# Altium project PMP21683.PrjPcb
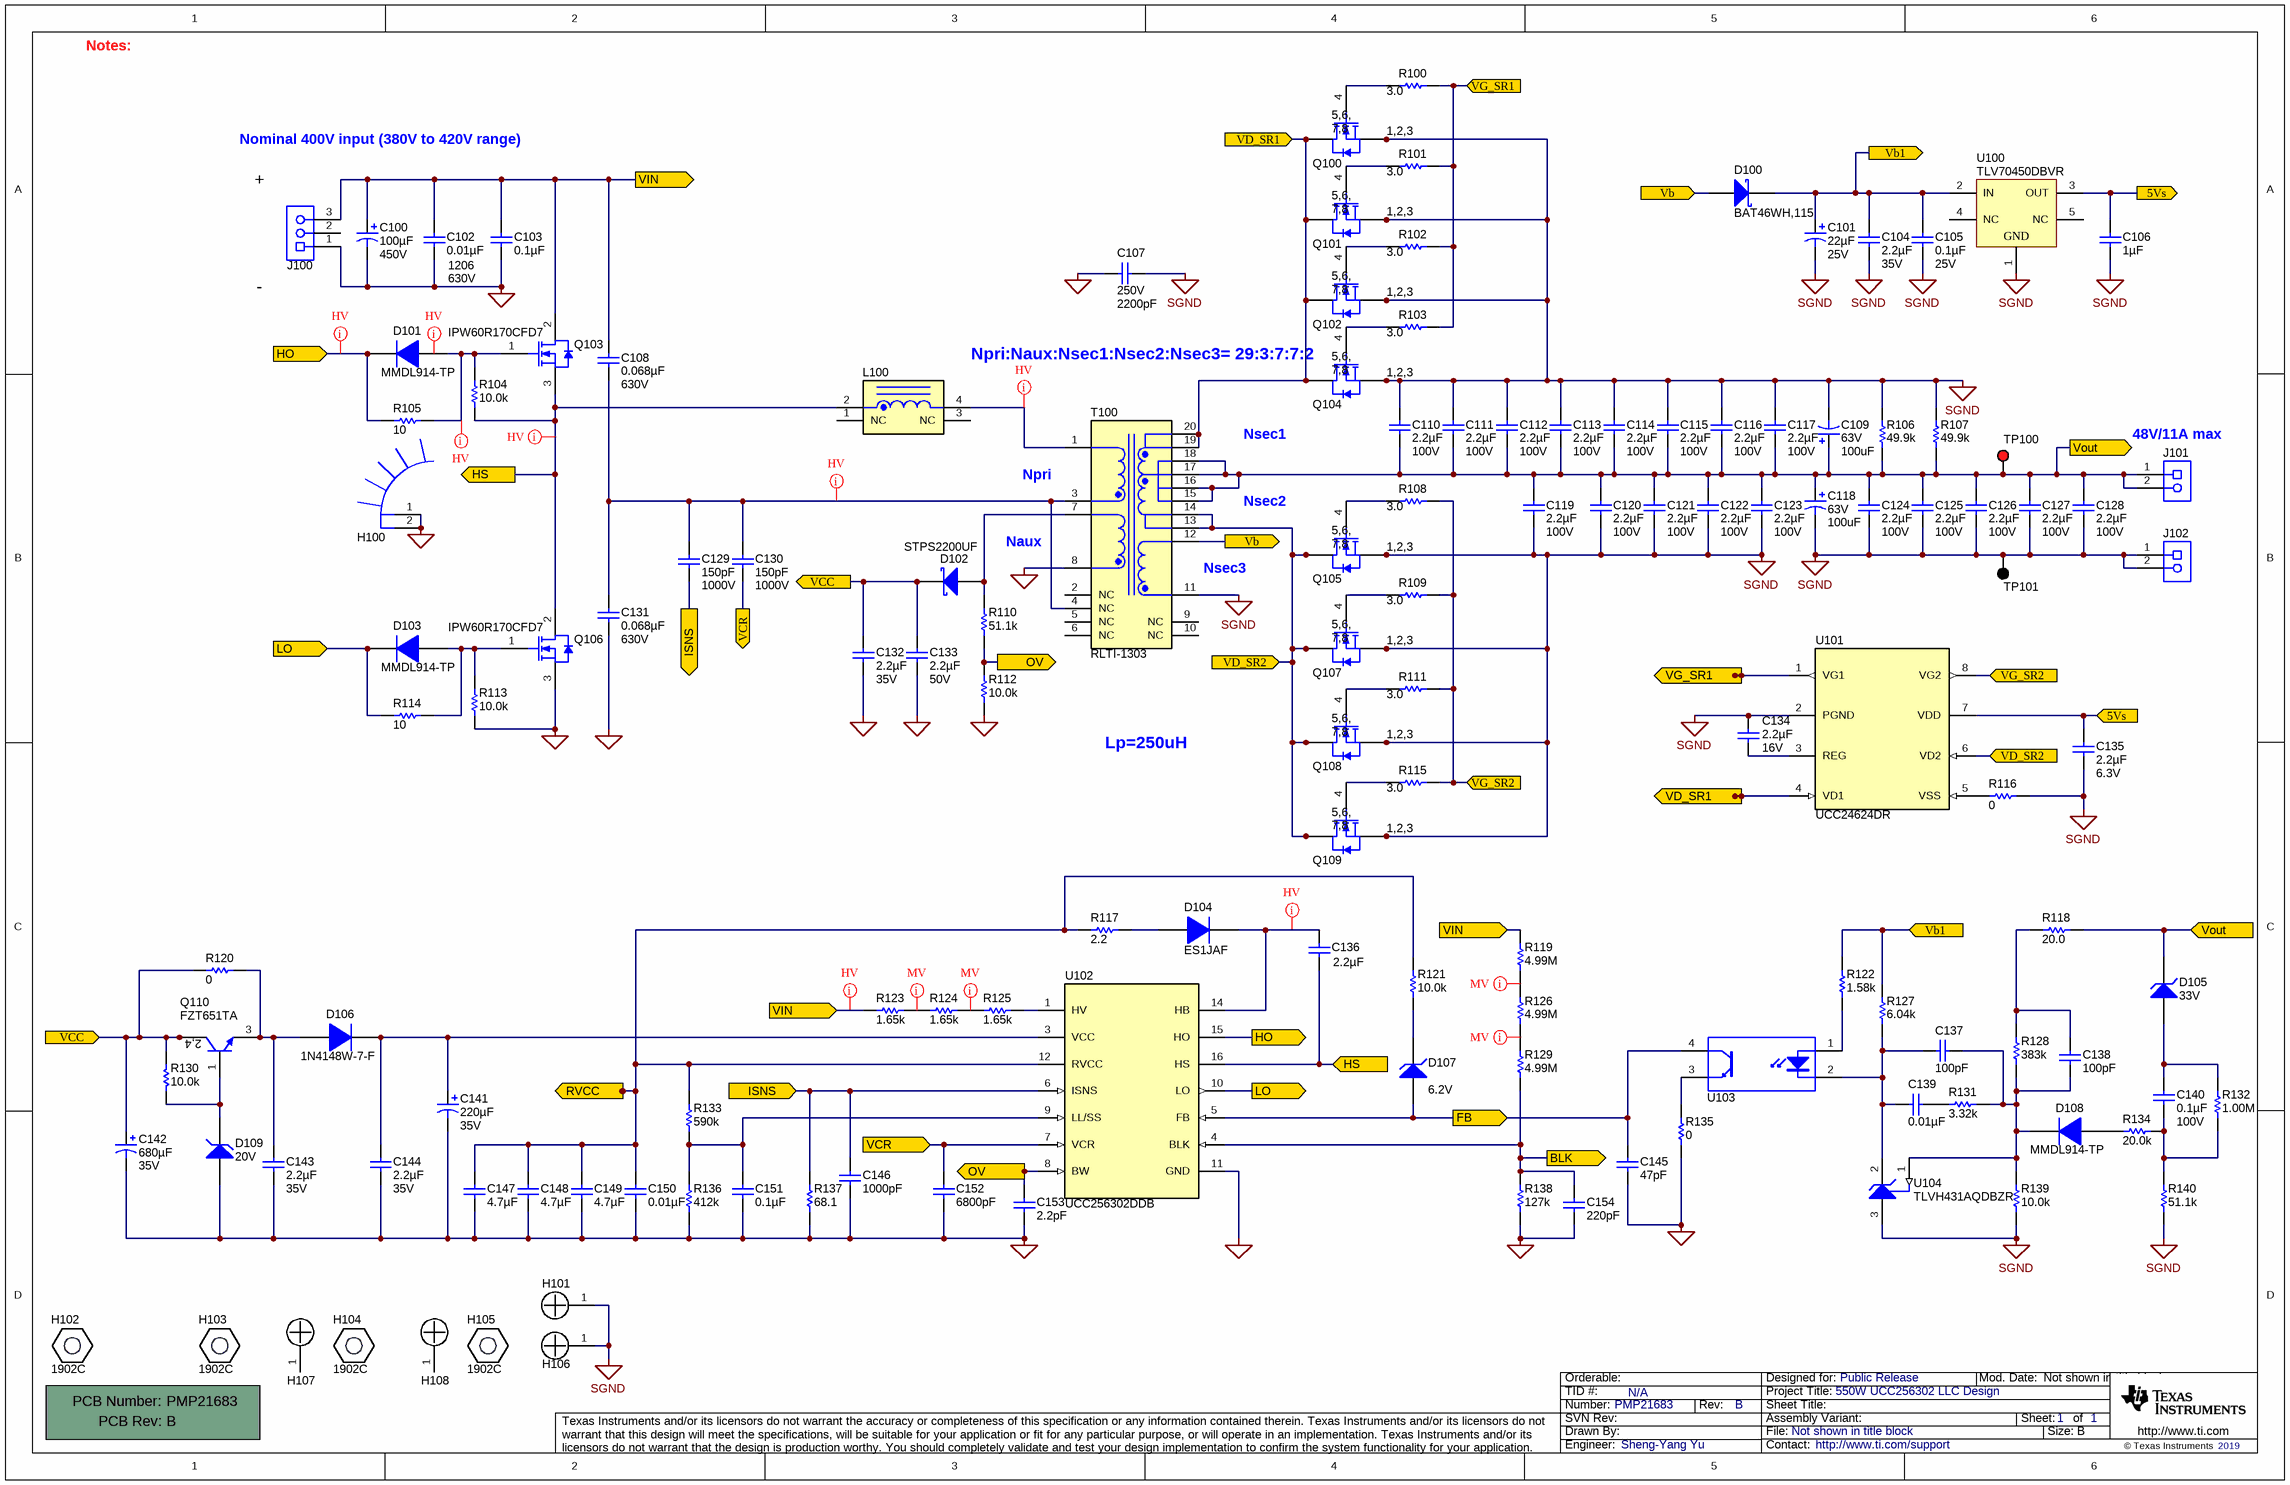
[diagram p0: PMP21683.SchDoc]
CopyrightYear: 2019; PCB_Layout: Sheng-Yang Yu; PCB_Rev: B; PRJ_Customer: Public Release; PRJ_Engineer: Sheng-Yang Yu; PRJ_Number: PMP21683; PRJ_Title: 550W UCC256302 LLC Design; SCH_Rev: B; TechSupport: http://www.ti.com/support; TID: N/A
1 sheet, 139 parts. Net scope: flat (ports and power ports of the same name join across sheets).
Board file: PMP21683.PcbDoc

## Sheet PMP21683.SchDoc
size 431 x 279 mm; Date: Not shown in title block; ApprovedBy: Not shown in title block; CheckedBy: Not shown in title block; Author: Not shown in title block; CompanyName: Not shown in title block; Engineer: Not shown in title block; Organization: Not shown in title block; Address1: Not shown in title block; Address2: Not shown in title block; Address3: Not shown in title block; Address4: Not shown in title block; DocumentNumber: 1; Revision: Use project parameter SCH_Rev; SheetNumber: 1; SheetTotal: 1; PageSetup: Record=PageOptions¦CenterHorizontal=True¦CenterVertical=True¦PrintScale=1.00¦XCorrection=1.00¦YCorrection=1.00¦PrintKind=0¦BorderSize=5000000¦LeftOffset=0¦BottomOffset=0¦Orientation=2¦PaperLength=1000¦PaperWidth=1000¦Scale=100¦PaperSource=15¦PrintQuality=600¦MediaType=1¦DitherType=10¦PaperKind=Letter¦PrintScaleMode=1

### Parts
!PCB100  Printed Circuit Board  (value not drawn)  (mechanical)
C100  ValueDisplayed: 100µF  Value2: 450V  [VR_1600x2500]  (hidden comment: 860241480001)
C101  ValueDisplayed: 22µF  Value2: 25V  [ML_500x500]  (hidden comment: 25ML22MEFC5X5)
C102  ValueDisplayed: 0.01µF  Value2: 630V  [1206]  (hidden comment: GRM31BR72J103KW01L)
C103  ValueDisplayed: 0.1µF  [1812_254]  (hidden comment: C1812W104KDRACTU)
C104  ValueDisplayed: 2.2µF  Value2: 35V  [0603]  (hidden comment: GRM188R6YA225KA12D)
C105  ValueDisplayed: 0.1µF  Value2: 25V  [0603]  (hidden comment: 06033C104JAT2A)
C106  ValueDisplayed: 1µF  [0603]  (hidden comment: GRM185R61A105KE36D)
C107  VDC_V: 250V  ValueDisplayed: 2200pF  [CAPRD1000W60D1000H1400]  (hidden comment: DE1E3KX222MA5BA01)
C108  ValueDisplayed: 0.068µF  VDC_V: 630V  [WCAP-FTBP_1800x600x1200]  (hidden comment: 890303325004CS)
C109  VDC_V: 63V  ValueDisplayed: 100uF  [CR_1000x1270]  (hidden comment: PCR1J101MCL1GS)
C110  ValueDisplayed: 2.2µF  Value2: 100V  [1206_190]  (hidden comment: GRM31CR72A225KA73L)
C111  ValueDisplayed: 2.2µF  Value2: 100V  [1206_190]  (hidden comment: GRM31CR72A225KA73L)
C112  ValueDisplayed: 2.2µF  Value2: 100V  [1206_190]  (hidden comment: GRM31CR72A225KA73L)
C113  ValueDisplayed: 2.2µF  Value2: 100V  [1206_190]  (hidden comment: GRM31CR72A225KA73L)
C114  ValueDisplayed: 2.2µF  Value2: 100V  [1206_190]  (hidden comment: GRM31CR72A225KA73L)
C115  ValueDisplayed: 2.2µF  Value2: 100V  [1206_190]  (hidden comment: GRM31CR72A225KA73L)
C116  ValueDisplayed: 2.2µF  Value2: 100V  [1206_190]  (hidden comment: GRM31CR72A225KA73L)
C117  ValueDisplayed: 2.2µF  Value2: 100V  [1206_190]  (hidden comment: GRM31CR72A225KA73L)
C118  VDC_V: 63V  ValueDisplayed: 100uF  [CR_1000x1270]  (hidden comment: PCR1J101MCL1GS)
C119  ValueDisplayed: 2.2µF  Value2: 100V  [1206_190]  (hidden comment: GRM31CR72A225KA73L)
C120  ValueDisplayed: 2.2µF  Value2: 100V  [1206_190]  (hidden comment: GRM31CR72A225KA73L)
C121  ValueDisplayed: 2.2µF  Value2: 100V  [1206_190]  (hidden comment: GRM31CR72A225KA73L)
C122  ValueDisplayed: 2.2µF  Value2: 100V  [1206_190]  (hidden comment: GRM31CR72A225KA73L)
C123  ValueDisplayed: 2.2µF  Value2: 100V  [1206_190]  (hidden comment: GRM31CR72A225KA73L)
C124  ValueDisplayed: 2.2µF  Value2: 100V  [1206_190]  (hidden comment: GRM31CR72A225KA73L)
C125  ValueDisplayed: 2.2µF  Value2: 100V  [1206_190]  (hidden comment: GRM31CR72A225KA73L)
C126  ValueDisplayed: 2.2µF  Value2: 100V  [1206_190]  (hidden comment: GRM31CR72A225KA73L)
C127  ValueDisplayed: 2.2µF  Value2: 100V  [1206_190]  (hidden comment: GRM31CR72A225KA73L)
C128  ValueDisplayed: 2.2µF  Value2: 100V  [1206_190]  (hidden comment: GRM31CR72A225KA73L)
C129  ValueDisplayed: 150pF  Value2: 1000V  [1206]  (hidden comment: GRM31A7U3A151JW31D)
C130  ValueDisplayed: 150pF  Value2: 1000V  [1206]  (hidden comment: GRM31A7U3A151JW31D)
C131  ValueDisplayed: 0.068µF  VDC_V: 630V  [WCAP-FTBP_1800x600x1200]  (hidden comment: 890303325004CS)
C132  ValueDisplayed: 2.2µF  Value2: 35V  [0603]  (hidden comment: GRM188R6YA225KA12D)
C133  ValueDisplayed: 2.2µF  Value2: 50V  [1206_180]  (hidden comment: C3216X5R1H225K160AB)
C134  ValueDisplayed: 2.2µF  Value2: 16V  [0603]  (hidden comment: 885012106018)
C135  ValueDisplayed: 2.2µF  Value2: 6.3V  [0603]  (hidden comment: C0603C225K9PACTU)
C136  ValueDisplayed: 2.2µF  [1206]  (hidden comment: C1206C225K4RACTU)
C137  ValueDisplayed: 100pF  [0603]  (hidden comment: 06035A101JAT2A)
C138  ValueDisplayed: 100pF  [0603]  (hidden comment: 06035A101JAT2A)
C139  ValueDisplayed: 0.01µF  [0603]  (hidden comment: 885012206040)
C140  ValueDisplayed: 0.1µF  Value2: 100V  [1206]  (hidden comment: GRM319R72A104KA01D)
C141  ValueDisplayed: 220µF  Value2: 35V  [KL_1000x2000]  (hidden comment: 860080575012)
C142  ValueDisplayed: 680µF  Value2: 35V  [HW_1000x2000]  (hidden comment: 860040575012)
C143  ValueDisplayed: 2.2µF  Value2: 35V  [0603]  (hidden comment: GRM188R6YA225KA12D)
C144  ValueDisplayed: 2.2µF  Value2: 35V  [0603]  (hidden comment: GRM188R6YA225KA12D)
C145  ValueDisplayed: 47pF  [0603]  (hidden comment: GRM1885C1H470FA01J)
C146  ValueDisplayed: 1000pF  [0603]  (hidden comment: C0603X102K5RACTU)
C147  ValueDisplayed: 4.7µF  [0603]  (hidden comment: GRM188R61C475KAAJ)
C148  ValueDisplayed: 4.7µF  [0603]  (hidden comment: GRM188R61C475KAAJ)
C149  ValueDisplayed: 4.7µF  [0603]  (hidden comment: GRM188R61C475KAAJ)
C150  ValueDisplayed: 0.01µF  [0603]  (hidden comment: 06031C103JAT2A)
C151  ValueDisplayed: 0.1µF  [0603]  (hidden comment: 0603YC104JAT2A)
C152  ValueDisplayed: 6800pF  [0603]  (hidden comment: 06031C682KAT2A)
C153  ValueDisplayed: 2.2pF  [0603]  (hidden comment: 06035A2R2CAT2A)
C154  ValueDisplayed: 220pF  [0603]  (hidden comment: GRM188R71H221KA01D)
D100  BAT46WH,115  [SOD-123F]
D101  MMDL914-TP  [SOD-323]
D102  STPS2200UF  [SMB_flat]
D103  MMDL914-TP  [SOD-323]
D104  ES1JAF  [SMAF]
D105  value 33V  [SOD-123]  (hidden comment: MMSZ5257B-7-F)
D106  1N4148W-7-F  [SOD-123]
D107  value 6.2V  [SOD-123]  (hidden comment: MMSZ5234B-7-F)
D108  MMDL914-TP  [SOD-323]
D109  value 20V  [SOD-323]  (hidden comment: MMSZ5250BS-7-F)
H100  513002B02500G  [Aavid_513002B02500G]  (value not drawn)
H101  NY PMS 440 0025 PH  [NY PMS 440 0025 PH]  (value not drawn)
H102  1902C  [Keystone_1902C]
H103  1902C  [Keystone_1902C]
H104  1902C  [Keystone_1902C]
H105  1902C  [Keystone_1902C]
H106  NY PMS 440 0025 PH  [NY PMS 440 0025 PH]  (value not drawn)
H107  NY PMS 440 0025 PH  [NY PMS 440 0025 PH]  (value not drawn)
H108  NY PMS 440 0025 PH  [NY PMS 440 0025 PH]  (value not drawn)
J100  282856-3  [TE_282856-3]  (value not drawn)
J101  1715721  [PhoenixContact_1715721]  (value not drawn)
J102  1715721  [PhoenixContact_1715721]  (value not drawn)
L100  RLTI-1304  [RLTI-1304]  (value not drawn)
Q100  BSC320N20NS3 G  [PG-TDSON-8]  (value not drawn)
Q101  BSC320N20NS3 G  [PG-TDSON-8]  (value not drawn)
Q102  BSC320N20NS3 G  [PG-TDSON-8]  (value not drawn)
Q103  PartNumber: IPW60R170CFD7  [TO-247]  (hidden comment: IPW60R075CPFKSA1)
Q104  BSC320N20NS3 G  [PG-TDSON-8]  (value not drawn)
Q105  BSC320N20NS3 G  [PG-TDSON-8]  (value not drawn)
Q106  PartNumber: IPW60R170CFD7  [TO-247]  (hidden comment: IPW60R075CPFKSA1)
Q107  BSC320N20NS3 G  [PG-TDSON-8]  (value not drawn)
Q108  BSC320N20NS3 G  [PG-TDSON-8]  (value not drawn)
Q109  BSC320N20NS3 G  [PG-TDSON-8]  (value not drawn)
Q110  FZT651TA  [SOT-223]
R100  ValueDisplayed: 3.0  [0402]  (hidden comment: CRCW04023R00JNED)
R101  ValueDisplayed: 3.0  [0402]  (hidden comment: CRCW04023R00JNED)
R102  ValueDisplayed: 3.0  [0402]  (hidden comment: CRCW04023R00JNED)
R103  ValueDisplayed: 3.0  [0402]  (hidden comment: CRCW04023R00JNED)
R104  ValueDisplayed: 10.0k  [0805_HV]  (hidden comment: RG2012P-103-B-T5)
R105  ValueDisplayed: 10  [0805_HV]  (hidden comment: RC0805JR-0710RL)
R106  ValueDisplayed: 49.9k  [1206]  (hidden comment: CRCW120649K9FKEA)
R107  ValueDisplayed: 49.9k  [1206]  (hidden comment: CRCW120649K9FKEA)
R108  ValueDisplayed: 3.0  [0402]  (hidden comment: CRCW04023R00JNED)
R109  ValueDisplayed: 3.0  [0402]  (hidden comment: CRCW04023R00JNED)
R110  ValueDisplayed: 51.1k  [0603]  (hidden comment: CRCW060351K1FKEA)
R111  ValueDisplayed: 3.0  [0402]  (hidden comment: CRCW04023R00JNED)
R112  ValueDisplayed: 10.0k  [0603]  (hidden comment: RCG060310K0FKEA)
R113  ValueDisplayed: 10.0k  [0805_HV]  (hidden comment: RG2012P-103-B-T5)
R114  ValueDisplayed: 10  [0805_HV]  (hidden comment: RC0805JR-0710RL)
R115  ValueDisplayed: 3.0  [0402]  (hidden comment: CRCW04023R00JNED)
R116  ValueDisplayed: 0  [0603]  (hidden comment: RMCF0603ZT0R00)
R117  ValueDisplayed: 2.2  [0603]  (hidden comment: CRCW06032R20JNEA)
R118  ValueDisplayed: 20.0  [0603]  (hidden comment: CRCW060320R0FKEA)
R119  ValueDisplayed: 4.99M  [1206]  (hidden comment: CRCW12064M99FKEA)
R120  ValueDisplayed: 0  [2010]  (hidden comment: CRCW20100000Z0EF)
R121  ValueDisplayed: 10.0k  [0603]  (hidden comment: ERJ-3EKF1002V)
R122  ValueDisplayed: 1.58k  [0603]  (hidden comment: RG1608P-1581-B-T5)
R123  ValueDisplayed: 1.65k  [1206]  (hidden comment: CRCW12061K65FKEA)
R124  ValueDisplayed: 1.65k  [1206]  (hidden comment: CRCW12061K65FKEA)
R125  ValueDisplayed: 1.65k  [1206]  (hidden comment: CRCW12061K65FKEA)
R126  ValueDisplayed: 4.99M  [1206]  (hidden comment: CRCW12064M99FKEA)
R127  ValueDisplayed: 6.04k  [0603]  (hidden comment: CRCW06036K04FKEA)
R128  ValueDisplayed: 383k  [0603]  (hidden comment: CRCW0603383KFKEA)
R129  ValueDisplayed: 4.99M  [1206]  (hidden comment: CRCW12064M99FKEA)
R130  ValueDisplayed: 10.0k  [0603]  (hidden comment: CRCW060310K0FKEA)
R131  ValueDisplayed: 3.32k  [0603]  (hidden comment: CRCW06033K32FKEA)
R132  ValueDisplayed: 1.00M  [1206]  (hidden comment: CRCW12061M00FKEA)
R133  ValueDisplayed: 590k  [0603]  (hidden comment: CRCW0603590KFKEA)
R134  ValueDisplayed: 20.0k  [0603]  (hidden comment: RC0603FR-0720KL)
R135  ValueDisplayed: 0  [5108]  (hidden comment: 5108)
R136  ValueDisplayed: 412k  [0603]  (hidden comment: CRCW0603412KFKEA)
R137  ValueDisplayed: 68.1  [0603]  (hidden comment: CRCW060368R1FKEA)
R138  ValueDisplayed: 127k  [0603]  (hidden comment: CRCW0603127KFKEA)
R139  ValueDisplayed: 10.0k  [0603]  (hidden comment: RCG060310K0FKEA)
R140  ValueDisplayed: 51.1k  [0603]  (hidden comment: CRCW060351K1FKEA)
T100  RLTI-1303  [Renco_RLTI-1303]
TP100  5000  [Keystone5000]  (value not drawn)
TP101  5011  [Keystone5011]  (value not drawn)
U100  TLV70450DBVR  [DBV0005A_N]
U101  UCC24624DR  [D0008A_N]
U102  UCC256302DDB  [DDB0014A]
U103  VO618A-3  [DIP-4]  (value not drawn)
U104  TLVH431AQDBZR  [DBZ0003A_N]

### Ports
5Vs (in), 5Vs (out), BLK (out), FB (out), HO (in), HO (out), HS (in), HS (out), ISNS (in), ISNS (out), LO (in), LO (out), OV (in), OV (out), RVCC (out), Vb1 (in), Vb1 (out), Vb (in), Vb (out), VCC (in), VCC (out), VCR (in), VCR (out), VD_SR1 (in), VD_SR2 (in), VG_SR1 (in), VG_SR1 (out), VG_SR2 (in), VIN (in), VIN (out), Vout, Vout (out)

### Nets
GND: C100.2(-) C102.2 C103.2 C107.2 C131.2 C132.1 C133.2 C141.2(-) C142.2(-) C143.1 C144.1 C145.2 C146.2 C147.2 C148.2 C149.2 C150.2 C151.2 C152.2 C153.2 C154.2 D109.2(A) H100.1 H100.2 J100.1 Q106.3(S) R112.1 R113.1 R135.1 R136.1 R137.1 R138.1 T100.8 U102.11(GND)
SGND: C101.2(-) C104.1 C105.1 C106.2 C107.1 C109.2(-) C110.2 C111.2 C112.2 C113.2 C114.2 C115.2 C116.2 C117.2 C118.2(-) C119.1 C120.1 C121.1 C122.1 C123.1 C124.1 C125.1 C126.1 C127.1 C128.1 C134.1 C135.2 H101.1 H106.1 J102.1 J102.2 Q100.1(S) Q100.2(S) Q100.3(S) Q101.1(S) Q101.2(S) Q101.3(S) Q102.1(S) Q102.2(S) Q102.3(S) Q104.1(S) Q104.2(S) Q104.3(S) Q105.1(S) Q105.2(S) Q105.3(S) Q107.1(S) Q107.2(S) Q107.3(S) Q108.1(S) Q108.2(S) Q108.3(S) Q109.1(S) Q109.2(S) Q109.3(S) R106.2 R107.2 R116.2 R139.1 R140.1 T100.11 TP101.1 U100.1(GND) U101.2(PGND) U104.3(ANODE)
5Vs: C106.1 C135.1 U100.3(OUT) U101.7(VDD) ; port 5Vs
BLK: C154.1 R129.1 R138.2 U102.4(BLK) ; port BLK
FB: C145.1 D107.2(A) U102.5(FB) U103.4(C) ; port FB
HO: D101.1(K) R105.1 U102.15(HO) ; port HO
HS: C136.2 L100.2 Q103.3(S) Q106.2(D) R104.1 U102.16(HS) ; port HS
ISNS: C129.2 C146.1 R137.2 U102.6(ISNS) ; port ISNS
LO: D103.1(K) R114.1 U102.10(LO) ; port LO
OV: C153.1 R110.1 R112.2 U102.8(BW) ; port OV
RVCC: C147.1 C148.1 C149.1 C150.1 R117.1 R121.2 R133.2 U102.12(RVCC) ; port RVCC
Vb: D100.2(A) T100.12 ; port Vb
Vb1: C101.1(+) C104.2 C105.2 D100.1(K) R122.2 R127.2 U100.2(IN) ; port Vb1
VCC: C132.2 C133.1 C142.1(+) D102.1(K) Q110.2(C) Q110.4(C) R120.1 R130.2 ; port VCC
VCR: C130.2 C152.1 U102.7(VCR) ; port VCR
VD_SR1: Q100.5(D) Q100.6(D) Q100.7(D) Q100.8(D) Q100.9(D) Q101.5(D) Q101.6(D) Q101.7(D) Q101.8(D) Q101.9(D) Q102.5(D) Q102.6(D) Q102.7(D) Q102.8(D) Q102.9(D) Q104.5(D) Q104.6(D) Q104.7(D) Q104.8(D) Q104.9(D) T100.19 T100.20 U101.4(VD1) ; port VD_SR1
VD_SR2: Q105.5(D) Q105.6(D) Q105.7(D) Q105.8(D) Q105.9(D) Q107.5(D) Q107.6(D) Q107.7(D) Q107.8(D) Q107.9(D) Q108.5(D) Q108.6(D) Q108.7(D) Q108.8(D) Q108.9(D) Q109.5(D) Q109.6(D) Q109.7(D) Q109.8(D) Q109.9(D) T100.13 T100.14 U101.6(VD2) ; port VD_SR2
VG_SR1: R100.2 R101.2 R102.2 R103.2 U101.1(VG1) ; port VG_SR1
VG_SR2: R108.2 R109.2 R111.2 R115.2 U101.8(VG2) ; port VG_SR2
VIN: C100.1(+) C102.1 C103.1 C108.1 J100.3 Q103.2(D) R119.2 R123.2 ; port VIN
Vout: C109.1(+) C110.1 C111.1 C112.1 C113.1 C114.1 C115.1 C116.1 C117.1 C118.1(+) C119.2 C120.2 C121.2 C122.2 C123.2 C124.2 C125.2 C126.2 C127.2 C128.2 D105.1(K) J101.1 J101.2 R106.1 R107.1 R118.1 T100.15 T100.16 T100.17 T100.18 TP100.1 ; port Vout
NetC108_2: C108.2 C129.1 C130.1 C131.1 T100.3 T100.4(NC)
NetC134_2: C134.2 U101.3(REG)
NetC136_1: C136.1 D104.1(K) U102.14(HB)
NetC137_1: C137.1 C139.2 R127.1 U103.2(K) U104.2(CATHODE)
NetC137_2: C137.2 C138.1 D108.1(K) R128.1 R131.2 R139.2 U104.1(REF)
NetC138_2: C138.2 R118.2 R128.2
NetC139_1: C139.1 R131.1
NetC140_1: C140.1 D105.2(A) R132.2
NetC140_2: C140.2 R132.1 R134.2 R140.2
NetC141_1: C141.1(+) C144.2 D106.1(K) U102.3(VCC)
NetC143_2: C143.2 D106.2(A) Q110.3(E) R120.2
NetC151_1: C151.1 R133.1 R136.2 U102.9(LL/SS)
NetD101_2: D101.2(A) Q103.1(G) R104.2 R105.2
NetD102_2: D102.2(A) R110.2 T100.7
NetD103_2: D103.2(A) Q106.1(G) R113.2 R114.2
NetD104_2: D104.2(A) R117.2
NetD107_1: D107.1(K) R121.1
NetD108_2: D108.2(A) R134.1
NetD109_1: D109.1(K) Q110.1(B) R130.1
NetL100_4: L100.4 T100.1
NetQ100_4: Q100.4(G) R100.1
NetQ101_4: Q101.4(G) R101.1
NetQ102_4: Q102.4(G) R102.1
NetQ104_4: Q104.4(G) R103.1
NetQ105_4: Q105.4(G) R108.1
NetQ107_4: Q107.4(G) R109.1
NetQ108_4: Q108.4(G) R111.1
NetQ109_4: Q109.4(G) R115.1
NetR116_1: R116.1 U101.5(VSS)
NetR119_1: R119.1 R126.2
NetR122_1: R122.1 U103.1(A)
NetR123_1: R123.1 R124.2
NetR124_1: R124.1 R125.2
NetR125_1: R125.1 U102.1(HV)
NetR126_1: R126.1 R129.2
NetR135_2: R135.2 U103.3(E)

Not connected (* = marked no-connect by the designer): H107 1; H108 1; J100 2; L100 1(NC) 3(NC); T100 2(NC) 5(NC) 6(NC) 9(NC) 10(NC); U100 4(NC) 5(NC)

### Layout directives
net class MV: NetR119_1, NetR123_1, NetR124_1, NetR126_1
net class HV: (no net found under the mark), HO, HS, NetC108_2, NetC136_1, NetD101_2, NetL100_4, VIN

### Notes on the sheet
- Notes:
- Nominal 400V input (380V to 420V range)
- +
- -
- Npri:Naux:Nsec1:Nsec2:Nsec3= 29:3:7:7:2
- Nsec1
- (near J101) 48V/11A max
- (near T100) Npri
- Nsec2
- Naux
- (near T100) Nsec3
- Lp=250uH

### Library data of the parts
!PCB100 = CMP-0003618-2: Manufacturer: Any; PartNumber: PMP21683
C100 = UVR2A471MHD: CAP ALUM 100UF 20% 450V RADIAL; Manufacturer: Wurth; Polarized: Y; CompType: Capacitor; U/M: EA; Cap_F: 0.00047; Tolerance_%: 20; VDC_V: 450; IRMS_A: 1; TaMin_C: -40; TaMax_C: 85; Cap_Case: 16x25mm; SizeAreaWB_mm2: 324; SizeArea_mm2: 256; SizeX_mm: 16; SizeZ_mm: 27; AEC Category: Q200; AEC Qualified: N
C101 = 25ML22MEFC5X5: CAP, AL, 22 µF, 25 V, +/- 20%, TH; Manufacturer: Rubycon; Polarized: Y; CompType: Capacitor; Value: 22uF; U/M: EA; Cap_F: 0.000022; Tolerance_%: 20; VDC_V: 25; IRMS_A: 0.042; TaMin_C: -40; TaMax_C: 105; Cap_Case: 5x5; SizeAreaWB_mm2: 49; SizeX_mm: 5; SizeZ_mm: 6.5; AEC Category: Q200; Green_Lifecycle: Not Set; Green_REACh: Incomplete
C102 = GRM31BR72J103KW01L: CAP, CERM, 0.01uF, 630V, +/-10%, X7R, 1206; Manufacturer: MuRata; Polarized: N; CompType: Capacitor; U/M: EA; Cap_F: 0.00000001; Tolerance_%: 10; Value1: Unknown; VDC_V: 630; TaMin_C: -55; TaMax_C: 125
C103 = C1812W104KDRACTU: CAP, CERM, 0.1 µF, 1000 V, +/- 10%, X7R, 1812; Manufacturer: Kemet; Polarized: N; CompType: Capacitor; Value: 0.1uF; U/M: EA; Cap_F: 0.0000001; Tolerance_%: 10; Value1: Unknown; VDC_V: 1000; Value2: 1000V; TaMin_C: -55; TaMax_C: 125; Cap_Case: 1812; AEC Category: Q200
C104 C132 C143 C144 = GRM188R6YA225KA12D: CAP, CERM, 2.2 µF, 35 V, +/- 10%, X5R, 0603; Manufacturer: MuRata; Polarized: N; CompType: Capacitor; Value: 2.2uF; U/M: EA; Cap_F: 0.0000022; Tolerance_%: 10; Value1: Unknown; VDC_V: 35; TaMin_C: -55; TaMax_C: 85; AEC Category: Q200
C105 = 06033C104JAT2A: CAP, CERM, 0.1 µF, 25 V,+/- 5%, X7R, 0603; Manufacturer: AVX; Polarized: N; CompType: Capacitor; Value: 0.1uF; U/M: EA; Cap_F: 0.0000001; Tolerance_%: 5; ESR_ohm: 0.05; Value1: 0.05 ohm; VDC_V: 25; TaMin_C: -55; TaMax_C: 125; SizeArea_mm2: 1.28; SizeAreaWB_mm2: 4.68; SizeX_mm: 1.6; SizeY_mm: 0.8; SizeZ_mm: 1; AEC Category: Q200; Green_Lifecycle: Active; Green_REACh: Passed
C106 = GRM185R61A105KE36D: CAP, CERM, 1 µF, 10 V,+/- 10%, X5R, 0603; Manufacturer: MuRata; Polarized: N; CompType: Capacitor; Value: 1uF; U/M: EA; Cap_F: 0.000001; Tolerance_%: 10; Value2: 10V; TaMin_C: -55; TaMax_C: 85; SizeArea_mm2: 1.28; SizeAreaWB_mm2: 4.68; SizeX_mm: 1.6; SizeY_mm: 0.8; SizeZ_mm: 1; AEC Category: Q200; Green_Lifecycle: Not Set; Green_REACh: Incomplete
C107 = CMP-0009602-2: CAP, CERM, 2200 pF, 250 V, +/- 20%, E, Disc 10x8mm; Manufacturer: MuRata; TaMin_C: -25°C; Polarized: N; SizeAreaWB_mm2: 120; Value1: Unknown; U/M: EA; Value: 2200pF; TaMax_C: 85°C; SizeZ_mm: 14; SizeX_mm: 10; SizeY_mm: 8; SizeArea_mm2: 80; CompType: Capacitor; Cap_F: 2.2nF; AEC Category: Q200
C108 C131 = CMP-0085305-1: CAP, Film, 0.068 µF, 630 V,+/- 5%, 0.10518 ohm, TH; Manufacturer: Wurth Elektronik; SizeZ_mm: 13; TaMax_C: 105°C; Polarized: N; Cap_Case: 18x6x12mm; CompType: Capacitor; AEC Category: Q200; SizeAreaWB_mm2: 160; SizeY_mm: 6; Value: 0.068uF; TaMin_C: -40°C; Cap_F: 68nF; SizeX_mm: 18; SizeArea_mm2: 108
C109 C118 = CMP-0012274-3: CAP, Aluminum Polymer, 100 uF, 63 V, +/- 20%, 0.024 ohm, SMD, 2-Leads, Dia 10.5mm, Pin Spacing 8mm SMD; Manufacturer: Nichicon; TaMin_C: -55°C; ESR_ohm: 0.024; Polarized: Y; Value: 100uF; TaMax_C: 125°C; Cap_Case: 10x12.7mm; CompType: Capacitor; AEC Qualified: N; Cap_F: 100µF; IRMS_A: 3A; AEC Category: Q200
C110-C117 C119-C128 = GRM31CR72A225KA73L: CAP, CERM, 2.2 µF, 100 V, +/- 10%, X7R, 1206_190; Manufacturer: MuRata; Polarized: N; CompType: Capacitor; Value: 2.2uF; U/M: EA; Cap_F: 0.0000022; Tolerance_%: 10; Value1: Unknown; VDC_V: 100; TaMin_C: -55; TaMax_C: 125; Cap_Case: 1206; SizeArea_mm2: 5.12; SizeAreaWB_mm2: 10.92; SizeX_mm: 3.2; SizeY_mm: 1.6; SizeZ_mm: 1.9; AEC Category: Q200
C129 C130 = GRM31A7U3A151JW31D: CAP, CERM, 150 pF, 1000 V,+/- 5%, U2J, 1206; Manufacturer: MuRata; Polarized: N; CompType: Capacitor; Value: 150pF; U/M: EA; Cap_F: 0.00000000015; Tolerance_%: 5; VDC_V: 1000; TaMin_C: -55; TaMax_C: 125; SizeArea_mm2: 5.12; SizeAreaWB_mm2: 10.92; SizeX_mm: 3.2; SizeY_mm: 1.6; SizeZ_mm: 1.35; AEC Category: Q200
C133 = C3216X5R1H225K160AB: CAP, CERM, 2.2 µF, 50 V,+/- 10%, X5R, 1206; Manufacturer: TDK; Polarized: N; CompType: Capacitor; Value: 2.2uF; U/M: EA; Cap_F: 0.0000022; Tolerance_%: 10; ESR_ohm: 0.005887; Value1: 0.005887 ohm; VDC_V: 50; IRMS_A: 2.99226; TaMin_C: -55; TaMax_C: 85; Cap_Case: 1206; SizeArea_mm2: 5.12; SizeAreaWB_mm2: 10.92; SizeX_mm: 3.2; SizeY_mm: 1.6; SizeZ_mm: 1.8; AEC Category: Q200
C134 = 885012106018: CAP, CERM, 2.2 µF, 16 V,+/- 20%, X5R, 0603; Manufacturer: Wurth Elektronik; Polarized: N; CompType: Capacitor; Value: 2.2uF; U/M: EA; Cap_F: 0.0000022; Tolerance_%: 20; VDC_V: 16; TaMin_C: -55; TaMax_C: 85; SizeArea_mm2: 1.28; SizeAreaWB_mm2: 4.68; SizeX_mm: 1.6; SizeY_mm: 0.8; SizeZ_mm: 1; AEC Category: Q200; Green_Lifecycle: Not Set; Green_REACh: Incomplete
C135 = C0603C225K9PACTU: CAP, CERM, 2.2 µF, 6.3 V,+/- 10%, X5R, 0603; Manufacturer: Kemet; Polarized: N; CompType: Capacitor; Value: 2.2uF; U/M: EA; Cap_F: 0.0000022; Tolerance_%: 10; VDC_V: 6.3; TaMin_C: -55; TaMax_C: 85; SizeArea_mm2: 1.28; SizeAreaWB_mm2: 4.68; SizeX_mm: 1.6; SizeY_mm: 0.8; SizeZ_mm: 1; AEC Category: Q200; Green_Lifecycle: Active; Green_REACh: Passed
C136 = C1206C225K4RACTU: CAP, CERM, 2.2 µF, 16 V, +/- 10%, X7R, 1206; Manufacturer: Kemet; Polarized: N; CompType: Capacitor; Value: 2.2uF; U/M: EA; Cap_F: 0.0000022; Tolerance_%: 10; ESR_ohm: 0.009; Value1: 0.009 ohm; VDC_V: 16; Value2: 16V; IRMS_A: 4.46; TaMin_C: -55; TaMax_C: 125; AEC Category: Q200; SizeArea_mm2: 5.12; SizeAreaWB_mm2: 10.92; SizeX_mm: 3.2; SizeY_mm: 1.6; SizeZ_mm: 1.35
C137 C138 = 06035A101JAT2A: CAP, CERM, 100 pF, 50 V,+/- 5%, C0G/NP0, 0603; Manufacturer: AVX; Polarized: N; CompType: Capacitor; Value: 100pF; U/M: EA; Cap_F: 0.0000000001; Tolerance_%: 5; ESR_ohm: 0.119; Value1: 0.119 ohm; VDC_V: 50; Value2: 50V; TaMin_C: -55; TaMax_C: 125; SizeArea_mm2: 1.28; SizeAreaWB_mm2: 4.68; SizeX_mm: 1.6; SizeY_mm: 0.8; SizeZ_mm: 1; AEC Category: Q200; Green_Lifecycle: Active; Green_REACh: Passed
C139 = 885012206040: CAP, CERM, 0.01 µF, 16 V,+/- 10%, X7R, 0603; Manufacturer: Wurth Elektronik; Polarized: N; CompType: Capacitor; Value: 0.01uF; U/M: EA; Cap_F: 0.00000001; Tolerance_%: 10; VDC_V: 16; Value2: 16V; TaMin_C: -55; TaMax_C: 125; SizeArea_mm2: 1.28; SizeAreaWB_mm2: 4.68; SizeX_mm: 1.6; SizeY_mm: 0.8; SizeZ_mm: 1; AEC Category: Q200; Green_Lifecycle: Active; Green_REACh: Passed
C140 = GRM319R72A104KA01D: CAP, CERM, 0.1 µF, 100 V,+/- 10%, X7R, 1206; Manufacturer: MuRata; Polarized: N; CompType: Capacitor; Value: 0.1uF; U/M: EA; Cap_F: 0.0000001; Tolerance_%: 10; VDC_V: 100; TaMin_C: -55; TaMax_C: 125; SizeArea_mm2: 5.12; SizeAreaWB_mm2: 10.92; SizeX_mm: 3.2; SizeY_mm: 1.6; SizeZ_mm: 1.35; AEC Category: Q200
C141 = UKL1V221KPD: CAP, AL, 220 µF, 35 V, +/- 10%, TH; Manufacturer: Wurth; Polarized: Y; CompType: Capacitor; Value: 220uF; U/M: EA; Cap_F: 0.00022; Tolerance_%: 10; VDC_V: 35; IRMS_A: 0.44; TaMin_C: -40; TaMax_C: 85; Cap_Case: 10x20mm; SizeAreaWB_mm2: 144; SizeArea_mm2: 100; SizeZ_mm: 21.5; AEC Category: Q200; AEC Qualified: N
C142 = UHW1V681MPD6: CAP, AL, 680 µF, 35 V, +/- 20%, 0.019 ohm, TH; Manufacturer: Wurth; Polarized: Y; CompType: Capacitor; Value: 680uF; U/M: EA; Cap_F: 0.00068; Tolerance_%: 20; VDC_V: 35; ESR_ohm: 0.019; IRMS_A: 2.5; TaMin_C: -40; TaMax_C: 105; Cap_Case: 10x20; SizeAreaWB_mm2: 144; SizeArea_mm2: 100; SizeX_mm: 10; SizeZ_mm: 22; AEC Category: Q200; AEC Qualified: N; Green_Lifecycle: Active; Green_REACh: Passed
C145 = GRM1885C1H470FA01J: CAP, CERM, 47 pF, 50 V, +/- 1%, C0G/NP0, 0603; Manufacturer: MuRata; Polarized: N; CompType: Capacitor; Value: 47pF; U/M: EA; Cap_F: 0.000000000047; Tolerance_%: 1; Value1: Unknown; VDC_V: 50; Value2: 50V; TaMin_C: -55; TaMax_C: 125; AEC Category: Q200
C146 = C0603X102K5RACTU: CAP, CERM, 1000 pF, 50 V,+/- 10%, X7R, 0603; Manufacturer: Kemet; Polarized: N; CompType: Capacitor; Value: 1000pF; U/M: EA; Cap_F: 0.000000001; Tolerance_%: 10; VDC_V: 50; Value2: 50V; TaMin_C: -55; TaMax_C: 125; SizeArea_mm2: 1.28; SizeAreaWB_mm2: 4.68; SizeX_mm: 1.6; SizeY_mm: 0.8; SizeZ_mm: 1; AEC Category: Q200; Green_Lifecycle: Active; Green_REACh: Passed
C147-C149 = GRM188R61C475KAAJ: CAP, CERM, 4.7 µF, 16 V, +/- 10%, X5R, 0603; Manufacturer: MuRata; Polarized: N; CompType: Capacitor; Value: 4.7uF; U/M: EA; Cap_F: 0.0000047; Tolerance_%: 10; Value1: Unknown; VDC_V: 16; Value2: 16V; TaMin_C: -55; TaMax_C: 85; AEC Category: Q200
C150 = 06031C103JAT2A: CAP, CERM, 0.01 µF, 100 V,+/- 5%, X7R, 0603; Manufacturer: AVX; Polarized: N; CompType: Capacitor; Value: 0.01uF; U/M: EA; Cap_F: 0.00000001; Tolerance_%: 5; ESR_ohm: 0.098; Value1: 0.098 ohm; VDC_V: 100; Value2: 100V; TaMin_C: -55; TaMax_C: 125; SizeArea_mm2: 1.28; SizeAreaWB_mm2: 4.68; SizeX_mm: 1.6; SizeY_mm: 0.8; SizeZ_mm: 1; AEC Category: Q200; Green_Lifecycle: Active; Green_REACh: Passed
C151 = 0603YC104JAT2A: CAP, CERM, 0.1 µF, 16 V,+/- 5%, X7R, 0603; Manufacturer: AVX; Polarized: N; CompType: Capacitor; Value: 0.1uF; U/M: EA; Cap_F: 0.0000001; Tolerance_%: 5; ESR_ohm: 0.039; Value1: 0.039 ohm; VDC_V: 16; Value2: 16V; TaMin_C: -55; TaMax_C: 125; SizeArea_mm2: 1.28; SizeAreaWB_mm2: 4.68; SizeX_mm: 1.6; SizeY_mm: 0.8; SizeZ_mm: 1; AEC Category: Q200; Green_Lifecycle: Active; Green_REACh: Passed
C152 = 06031C682KAT2A: CAP, CERM, 6800 pF, 100 V,+/- 10%, X7R, 0603; Manufacturer: AVX; Polarized: N; CompType: Capacitor; Value: 6800pF; U/M: EA; Cap_F: 0.0000000068; Tolerance_%: 10; ESR_ohm: 0.115; Value1: 0.115 ohm; VDC_V: 100; Value2: 100V; TaMin_C: -55; TaMax_C: 125; SizeArea_mm2: 1.28; SizeAreaWB_mm2: 4.68; SizeX_mm: 1.6; SizeY_mm: 0.8; SizeZ_mm: 1; AEC Category: Q200; Green_Lifecycle: Not Set; Green_REACh: Incomplete
C153 = 06035A2R2CAT2A: CAP, CERM, 2.2 pF, 50 V, +/- 11%, C0G/NP0, 0603; Manufacturer: AVX; Polarized: N; CompType: Capacitor; Value: 2.2pF; U/M: EA; Cap_F: 0.0000000000022; Tolerance_%: 11; ESR_ohm: 1.033; Value1: 1.033 ohm; VDC_V: 50; Value2: 50V; TaMin_C: -55; TaMax_C: 125; SizeArea_mm2: 1.28; SizeAreaWB_mm2: 4.68; SizeX_mm: 1.6; SizeY_mm: 0.8; SizeZ_mm: 1; AEC Category: Q200
C154 = GRM188R71H221KA01D: CAP, CERM, 220 pF, 50 V, +/- 10%, X7R, 0603; Manufacturer: MuRata; Polarized: N; CompType: Capacitor; Value: 220pF; U/M: EA; Cap_F: 0.00000000022; Tolerance_%: 10; Value1: Unknown; VDC_V: 50; Value2: 50V; TaMin_C: -55; TaMax_C: 125; AEC Category: Q200
D100 = BAT46WH,115: Diode, Schottky, 100 V, 0.25 A, SOD-123F; Manufacturer: Nexperia; U/M: EA; Vf_V: 0.85; Value: 100V; Value1: 0.25A; Value2: 0.85V; Io_A: 0.25; Vr_V: 100; TJmax_C: 150; SizeAreaWB_mm2: 11.7; SizeArea_mm2: 5.6; SizeX_mm: 3.5; SizeY_mm: 1.6; SizeZ_mm: 1.1; AEC Category: Q101; Green_Lifecycle: Not Set; Green_REACh: Incomplete
D101 D103 = MMDL914-TP: Diode, Switching, 100 V, 0.2 A, SOD-323; Manufacturer: Micro Commercial Components; U/M: EA; Vf_V: 1; Value: 100V; Value1: 0.2A; Value2: 1V; Io_A: 0.2; Vr_V: 100; TJmax_C: 150; SizeAreaWB_mm2: 8.695; SizeArea_mm2: 3.645; SizeX_mm: 2.7; SizeY_mm: 1.35; AEC Category: Q101; Green_Lifecycle: Not Set; Green_REACh: Incomplete
D102 = STPS2200UF: Diode, Schottky, 200 V, 2 A, SMB; Manufacturer: STMicroelectronics; U/M: EA; Vf_V: 0.8; Value: 200V; Value1: 2A; Value2: 0.8V; Io_A: 2; Vr_V: 200; TJmax_C: 175; SizeAreaWB_mm2: 41.34375; SizeArea_mm2: 19.39375; SizeX_mm: 5.35; SizeY_mm: 3.625; SizeZ_mm: 1.1; AEC Category: Q101; AEC Qualified: N; Green_Lifecycle: Not Set; Green_REACh: Incomplete
D104 = ES1JAF: Diode, Ultrafast, 600 V, 1 A, AEC-Q101, SMAF; Manufacturer: Fairchild Semiconductor; U/M: EA; Vf_V: 1.7; Value: 600V; Value1: 1A; Value2: 1.7V; Io_A: 1; Vr_V: 600; TJmax_C: 150; AEC Category: Q101; AEC Qualified: Y
D105 = CMP-0005762-2: Diode, Zener, 33 V, 500 mW, SOD-123; Manufacturer: Diodes Inc.; Power_W: 500mW; SizeAreaWB_mm2: 13.095; Value1: 0.5W; RJA_CperW: 350; U/M: EA; SizeZ_mm: 1.35; SizeX_mm: 3.85; SizeY_mm: 1.7; SizeArea_mm2: 6.545; AEC Category: Q101
D106 = 1N4148W-7-F: Diode, Ultrafast, 100 V, 0.15 A, SOD-123; Manufacturer: Diodes Inc.; U/M: EA; Vf_V: 1.25; Value: 100V; Value1: 0.15A; Value2: 1.25V; Io_A: 0.15; Vr_V: 100; TJmax_C: 150; SizeAreaWB_mm2: 13.095; SizeArea_mm2: 6.545; SizeX_mm: 3.85; SizeY_mm: 1.7; SizeZ_mm: 1.35; AEC Category: Q101
D107 = MMSZ5234B-7-F: Diode, Zener, 6.2 V, 500 mW, SOD-123; Manufacturer: Diodes Inc.; SymbolCreator: a0412235; U/M: EA; Power_W: 0.5; Vz_V: 6.2; Value1: 0.5W; RJA_CperW: 350; SizeAreaWB_mm2: 13.095; SizeArea_mm2: 6.545; SizeX_mm: 3.85; SizeY_mm: 1.7; SizeZ_mm: 1.35; AEC Category: Q101
D108 = MMDL914-TP: Diode, Switching, 100 V, 0.2 A, SOD-323; Manufacturer: Micro Commercial Components; U/M: EA; Vf_V: 1; Value: 100V; Value1: 0.2A; Value2: 1V; Io_A: 0.2; Vr_V: 100; TJmax_C: 150; SizeAreaWB_mm2: 8.695; SizeArea_mm2: 3.645; SizeX_mm: 2.7; SizeY_mm: 1.35; AEC Category: Q101
D109 = MMSZ5250BS-7-F: Diode, Zener, 20 V, 200 mW, SOD-323; Manufacturer: Diodes Inc.; SymbolCreator: a0412235; U/M: EA; Power_W: 0.2; Vz_V: 20; Value1: 0.2W; RJA_CperW: 350; SizeAreaWB_mm2: 8.695; SizeArea_mm2: 3.645; SizeX_mm: 2.7; SizeY_mm: 1.35; SizeZ_mm: 1; AEC Category: Q101
H100 = CMP-0082193-1: HEATSINK TO-220 W/PINS 1" TALL; Manufacturer: Aavid
H101 H106-H108 = CMP-0003617-1: Machine Screw, Round, #4-40 x 1/4, Nylon, Philips panhead; Manufacturer: B&F Fastener Supply; CompType: Hardware
H102-H105 = CMP-0003610-1: Standoff, Hex, 0.5"L #4-40 Nylon; Manufacturer: Keystone; CompType: Hardware
J100 = 282856-3: Receptacle, 3x1, 5mm, R/A, TH; Manufacturer: TE Connectivity; SymbolCreator: a0412235; CompType: Terminal Block; Pitch_mm: 5; Gender: Female; Row_Count: 1; ContactFinish: Tin; Current_A: 24; Voltage_V: 300; Cert_UL: Y
J101 J102 = CMP-0055471-1: Terminal Block, 5.08 mm, 2x1, TH; Manufacturer: Phoenix Contact; Cert_VDE: Y; CNHeader: FALSE; Current_A: 17.5A; Green_Lifecycle: Not Set; Gender: Female; Cert_CULUS: N; Green_REACh: Incomplete; Voltage_V: 400V; Row_Count: 1; Pitch_mm: 5.08; ContactFinish: Tin; CT: TRUE
L100 = CMP-0084749-1: Inductor, Toroid, 0.0345 ohm, TH; Manufacturer: Renco Electronics; AEC Qualified: N; SizeX_mm: 20.574; Value2: A; AEC Category: Q200; SizeY_mm: 31.75; SizeZ_mm: 35.56; SizeAreaWB_mm2: 761.8725; SizeArea_mm2: 653.2245; DCR_ohm: 0.0345
Q100-Q102 Q104 Q105 Q107-Q109 = CMP-0001075-2: MOSFET, N-CH, 200 V, 36 A, PG-TDSON-8; PartNumber: BSC350N20NSFD; Alternate Manufacturer: None; Manufacturer: Infineon Technologies; SizeZ_mm: 1.12; ChType: N; Value2: 22 nC; Value1: 0.03; VdsMax_V: 200V; SizeX_mm: 5.99; SizeY_mm: 4.9; Vgs_V: 20V; Value: 200V; Rdson45_ohm: 0.032; SizeArea_mm2: 29.351; AEC Category: Q101; IdsMax_A: 36A; SizeAreaWB_mm2: 55.131; U/M: EA; QgTyp_nC: 22
Q103 Q106 = CMP-0001179-3: MOSFET N-CH 600V TO247-3; Alternate Manufacturer: None; Manufacturer: Infineon Technologies; SizeZ_mm: 25; ChType: N; SizeX_mm: 15.6; SizeY_mm: 5; SizeArea_mm2: 78; AEC Category: Q101; SizeAreaWB_mm2: 123.2; ChMode: Enhancement
Q110 = FZT651TA, Zetex: Transistor, NPN, 60 V, 3 A, SOT-223; Manufacturer: Zetex; SymbolCreator: a0412235; PNP: 0; NPN: 1; Vceo_V: 60; Vcesat1_V: 0.43; Value: 60 V; IcRated_A: 3; Value1: 3 A; HfeMax: 300; TaMin_C: -55; TaMax_C: 150; SizeAreaWB_mm2: 76.5; SizeArea_mm2: 45.5; SizeX_mm: 6.5; SizeY_mm: 7; SizeZ_mm: 1.6; CompType: BJT; U/M: EA; AEC Category: Q101
R100-R103 R108 R109 R111 R115 = CRCW04023R00JNED: RES, 3.0, 5%, 0.063 W, 0402; Manufacturer: Vishay-Dale; CompType: Resistor; Value: 3.0; Res_ohm: 3; Value_Code: 3R00; Tolerance_%: 5; Power_W: 0.063; Value2: 0.063W; VDC_V: 50; TempCo: 200 ppm/C; SizeArea_mm2: 0.5; SizeX_mm: 1; SizeZ_mm: 0.6; EIA_Code: E24; U/M: EA; AEC Category: Q200
R104 R113 = RG2012P-103-B-T5: RES, 10.0 k, 0.1%, 0.125 W, 0805; Manufacturer: Susumu Co Ltd; CompType: Resistor; Value: 10.0k; Res_ohm: 10000; Value_Code: 10k0; Tolerance_%: 0.1; Power_W: 0.125; Value2: 0.125W; VDC_V: 100; TempCo: 25 ppm/C; SizeArea_mm2: 2.5; SizeX_mm: 2; SizeY_mm: 1.25; SizeZ_mm: 1.45; EIA_Code: E192; U/M: EA; AEC Category: Q200
R105 R114 = RC0805JR-0710RL: RES, 10, 5%, 0.125 W, 0805; Manufacturer: Yageo America; CompType: Resistor; Value: 10; Value_Code: 10R0; Tolerance_%: 5; Power_W: 0.125; Value2: 0.125W; VDC_V: 150; TempCo: 200 ppm/C; SizeArea_mm2: 2.5; SizeX_mm: 2; SizeY_mm: 1.25; SizeZ_mm: 1.45; EIA_Code: E24; U/M: EA; AEC Category: Q200; Green_Lifecycle: Active; Green_REACh: Passed
R106 R107 = CRCW120649K9FKEA: RES, 49.9 k, 1%, 0.25 W, 1206; Manufacturer: Vishay-Dale; CompType: Resistor; Value: 49.9k; Res_ohm: 49900; Value_Code: 49k9; Tolerance_%: 1; Power_W: 0.25; Value2: 0.25W; VDC_V: 200; TempCo: 100 ppm/C; SizeArea_mm2: 5.12; SizeX_mm: 3.2; SizeY_mm: 1.6; SizeZ_mm: 1.35; EIA_Code: E96; U/M: EA; AEC Category: Q200
R110 R140 = CRCW060351K1FKEA: RES, 51.1 k, 1%, 0.1 W, 0603; Manufacturer: Vishay-Dale; CompType: Resistor; Value: 51.1k; Res_ohm: 51100; Value_Code: 51k1; Tolerance_%: 1; Power_W: 0.1; Value2: 0.1W; VDC_V: 75; TempCo: 100 ppm/C; SizeArea_mm2: 1.28; SizeX_mm: 1.6; SizeY_mm: 0.8; EIA_Code: E96; U/M: EA; AEC Category: Q200; Green_Lifecycle: Active; Green_REACh: Passed
R112 R139 = RCG060310K0FKEA: RES, 10.0 k, 1%, 0.1 W, 0603; Manufacturer: Vishay Draloric; CompType: Resistor; Value: 10.0k; Res_ohm: 10000; Value_Code: 10k0; Tolerance_%: 1; Power_W: 0.1; Value2: 0.1W; VDC_V: 75; TempCo: 100 ppm/C; SizeArea_mm2: 1.28; SizeX_mm: 1.6; SizeY_mm: 0.8; EIA_Code: E96; U/M: EA; AEC Category: Q200; AEC Qualified: N
R116 = RMCF0603ZT0R00: RES, 0, 1%, 0.1 W, AEC-Q200 Grade 0, 0603; Manufacturer: Stackpole Electronics Inc; CompType: Resistor; Value: 0; Tolerance_%: 1; Power_W: 0.1; Value2: 0.1W; TempCo: ppm/C; SizeArea_mm2: 1.28; SizeX_mm: 1.6; SizeY_mm: 0.8; U/M: EA; AEC Category: Q200; AEC Qualified: Y; Green_Lifecycle: Active; Green_REACh: Passed
R117 = CRCW06032R20JNEA: RES, 2.2, 5%, 0.1 W, 0603; Manufacturer: Vishay-Dale; CompType: Resistor; Value: 2.2; Value_Code: 2R20; Tolerance_%: 5; Power_W: 0.1; Value2: 0.1W; VDC_V: 75; TempCo: 200 ppm/C; EIA_Code: E24; U/M: EA
R118 = CRCW060320R0FKEA: RES, 20.0, 1%, 0.1 W, 0603; Manufacturer: Vishay-Dale; CompType: Resistor; Value: 20.0; Res_ohm: 20; Value_Code: 20R0; Tolerance_%: 1; Power_W: 0.1; Value2: 0.1W; VDC_V: 75; TempCo: 100 ppm/C; SizeArea_mm2: 1.28; SizeX_mm: 1.6; SizeY_mm: 0.8; EIA_Code: E96; U/M: EA; AEC Category: Q200; Green_Lifecycle: Active; Green_REACh: Passed
R119 R126 R129 = CRCW12064M99FKEA: RES, 4.99 M, 1%, 0.25 W, 1206; Manufacturer: Vishay-Dale; CompType: Resistor; Value: 4.99Meg; Res_ohm: 4990000; Value_Code: 4M99; Tolerance_%: 1; Power_W: 0.25; Value2: 0.25W; VDC_V: 200; TempCo: 100 ppm/C; EIA_Code: E96; U/M: EA; AEC Category: Q200; SizeArea_mm2: 5.12; SizeX_mm: 3.2; SizeY_mm: 1.6; SizeZ_mm: 1.35
R120 = CRCW20100000Z0EF: RES, 0, 5%, 0.75 W, AEC-Q200 Grade 0, 2010; Manufacturer: Vishay-Dale; CompType: Resistor; Value: 0; Value_Code: 0000; Tolerance_%: 5; Power_W: 0.75; Value2: 0.75W; TempCo: ppm/C; SizeArea_mm2: 12.5; SizeY_mm: 2.5; SizeZ_mm: 1.66; EIA_Code: E24; U/M: EA; AEC Category: Q200; AEC Qualified: Y
R121 = ERJ-3EKF1002V: RES, 10.0 k, 1%, 0.1 W, 0603; Manufacturer: Panasonic; CompType: Resistor; Value: 10.0k; Res_ohm: 10000; Value_Code: 10k0; Tolerance_%: 1; Power_W: 0.1; Value2: 0.1W; VDC_V: 75; TempCo: 100 ppm/C; SizeArea_mm2: 1.28; SizeX_mm: 1.6; SizeY_mm: 0.8; EIA_Code: E96; U/M: EA; AEC Category: Q200; Green_Lifecycle: Active; Green_REACh: Passed
R122 = RG1608P-1581-B-T5: RES, 1.58 k, 0.1%, 0.1 W, 0603; Manufacturer: Susumu Co Ltd; CompType: Resistor; Value: 1.58k; Res_ohm: 1580; Value_Code: 1k58; Tolerance_%: 0.1; Value2: 0.1W; VDC_V: 75; TempCo: 25 ppm/C; SizeArea_mm2: 1.28; SizeX_mm: 1.6; SizeY_mm: 0.8; SizeZ_mm: 1; EIA_Code: E192; U/M: EA; AEC Category: Q200
R123-R125 = CRCW12061K65FKEA: RES, 1.65 k, 1%, 0.25 W, 1206; Manufacturer: Vishay-Dale; CompType: Resistor; Value: 1.65k; Res_ohm: 1650; Value_Code: 1k65; Tolerance_%: 1; Power_W: 0.25; Value2: 0.25W; VDC_V: 200; TempCo: 100 ppm/C; EIA_Code: E96; U/M: EA; AEC Category: Q200; SizeArea_mm2: 5.12; SizeX_mm: 3.2; SizeY_mm: 1.6; SizeZ_mm: 1.35
R127 = CRCW06036K04FKEA: RES, 6.04 k, 1%, 0.1 W, 0603; Manufacturer: Vishay-Dale; CompType: Resistor; Value: 6.04k; Res_ohm: 6040; Value_Code: 6k04; Tolerance_%: 1; Power_W: 0.1; Value2: 0.1W; VDC_V: 75; TempCo: 100 ppm/C; EIA_Code: E96; U/M: EA; AEC Category: Q200
R128 = CRCW0603383KFKEA: RES, 383 k, 1%, 0.1 W, 0603; Manufacturer: Vishay-Dale; CompType: Resistor; Value: 383k; Res_ohm: 383000; Tolerance_%: 1; Power_W: 0.1; Value2: 0.1W; VDC_V: 75; TempCo: 100 ppm/C; SizeArea_mm2: 1.28; SizeX_mm: 1.6; SizeY_mm: 0.8; EIA_Code: E96; U/M: EA; AEC Category: Q200
R130 = CRCW060310K0FKEA: RES, 10.0 k, 1%, 0.1 W, 0603; Manufacturer: Vishay-Dale; CompType: Resistor; Value: 10.0k; Res_ohm: 10000; Value_Code: 10k0; Tolerance_%: 1; Power_W: 0.1; Value2: 0.1W; VDC_V: 75; TempCo: 100 ppm/C; SizeArea_mm2: 1.28; SizeX_mm: 1.6; SizeY_mm: 0.8; EIA_Code: E96; U/M: EA; AEC Category: Q200; Green_Lifecycle: Active; Green_REACh: Passed
R131 = CRCW06033K32FKEA: RES, 3.32 k, 1%, 0.1 W, 0603; Manufacturer: Vishay-Dale; CompType: Resistor; Value: 3.32k; Res_ohm: 3320; Value_Code: 3k32; Tolerance_%: 1; Power_W: 0.1; Value2: 0.1W; VDC_V: 75; TempCo: 100 ppm/C; SizeArea_mm2: 1.28; SizeX_mm: 1.6; SizeY_mm: 0.8; EIA_Code: E96; U/M: EA; AEC Category: Q200; Green_Lifecycle: Active; Green_REACh: Passed
R132 = CRCW12061M00FKEA: RES, 1.00 M, 1%, 0.25 W, 1206; Manufacturer: Vishay-Dale; CompType: Resistor; Value: 1.00Meg; Res_ohm: 1000000; Value_Code: 1M00; Tolerance_%: 1; Power_W: 0.25; Value2: 0.25W; VDC_V: 200; TempCo: 100 ppm/C; SizeArea_mm2: 5.12; SizeX_mm: 3.2; SizeY_mm: 1.6; SizeZ_mm: 1.35; EIA_Code: E96; U/M: EA; AEC Category: Q200; Green_Lifecycle: Active; Green_REACh: Passed
R133 = CRCW0603590KFKEA: RES, 590 k, 1%, 0.1 W, 0603; Manufacturer: Vishay-Dale; CompType: Resistor; Value: 590k; Res_ohm: 590000; Tolerance_%: 1; Power_W: 0.1; Value2: 0.1W; VDC_V: 75; TempCo: 100 ppm/C; SizeArea_mm2: 1.28; SizeX_mm: 1.6; SizeY_mm: 0.8; EIA_Code: E96; U/M: EA; AEC Category: Q200; Green_Lifecycle: Active; Green_REACh: Passed
R134 = RC0603FR-0720KL: RES, 20.0 k, 1%, 0.1 W, 0603; Manufacturer: Yageo America; CompType: Resistor; Value: 20.0k; Res_ohm: 20000; Value_Code: 20k0; Tolerance_%: 1; Power_W: 0.1; Value2: 0.1W; VDC_V: 150; TempCo: 200 ppm/C; SizeArea_mm2: 1.28; SizeX_mm: 1.6; SizeY_mm: 0.8; EIA_Code: E96; U/M: EA; AEC Category: Q200; Green_Lifecycle: Active; Green_REACh: Passed
R135 = 5108: RES, 0, 1%, 0.5 W, 1206; Manufacturer: Keystone; CompType: Resistor; Value: 0; Tolerance_%: 1; Power_W: 0.5; Value2: 0.5W; TempCo: ppm/C; SizeArea_mm2: 5.185; SizeX_mm: 3.05; SizeY_mm: 1.7; SizeZ_mm: 0.84; U/M: EA; AEC Category: Q200; AEC Qualified: N
R136 = CRCW0603412KFKEA: RES, 412 k, 1%, 0.1 W, 0603; Manufacturer: Vishay-Dale; CompType: Resistor; Value: 412k; Res_ohm: 412000; Tolerance_%: 1; Power_W: 0.1; Value2: 0.1W; VDC_V: 75; TempCo: 100 ppm/C; SizeArea_mm2: 1.28; SizeX_mm: 1.6; SizeY_mm: 0.8; EIA_Code: E96; U/M: EA; AEC Category: Q200
R137 = CRCW060368R1FKEA: RES, 68.1, 1%, 0.1 W, 0603; Manufacturer: Vishay-Dale; CompType: Resistor; Value: 68.1; Value_Code: 68R1; Tolerance_%: 1; Power_W: 0.1; Value2: 0.1W; VDC_V: 75; TempCo: 100 ppm/C; SizeArea_mm2: 1.28; SizeX_mm: 1.6; SizeY_mm: 0.8; EIA_Code: E96; U/M: EA; AEC Category: Q200
R138 = CRCW0603127KFKEA: RES, 127 k, 1%, 0.1 W, 0603; Manufacturer: Vishay-Dale; CompType: Resistor; Value: 127k; Res_ohm: 127000; Tolerance_%: 1; Power_W: 0.1; Value2: 0.1W; VDC_V: 75; TempCo: 100 ppm/C; SizeArea_mm2: 1.28; SizeX_mm: 1.6; SizeY_mm: 0.8; EIA_Code: E96; U/M: EA; AEC Category: Q200; Green_Lifecycle: Active; Green_REACh: Passed
T100 = CMP-0084748-1: Transformer, 250 uH, TH; Manufacturer: Renco Electronics; SizeArea_mm2: 3240.3161; SizeY_mm: 52.07; Ns2toNp: 0.25; Lp: 250; Value: 250uH; AEC Category: Q200; AEC Qualified: N; SizeZ_mm: 25.4; LeakageInd_H: 6µH; Ind_H: 250µH; SizeX_mm: 62.23; SizeAreaWB_mm2: 3472.9161; DCR_ohm: 0.085; Rsec2_ohm: 5m
TP100 = 5000: Test Point, Miniature, Red, TH; Manufacturer: Keystone; CompType: Test Point Loop; ContactFinish: Silver
TP101 = 5011: Test Point, Multipurpose, Black, TH; Manufacturer: Keystone; CompType: Test Point Loop; ContactFinish: Silver
U100 = CMP-0035558-1: Single Output LDO, 150 mA, Fixed 5 V Output, 2.5 to 24 V Input, with Ultra-Low IQ, 5-pin SOT-23 (DBV), -40 to 125 degC, Green (RoHS & no Sb/Br); Manufacturer: Texas Instruments; Vout Adj(Max)(V): 5; Vin(Min)(V): 2.5; Vin(Max)(V): 24; Accuracy(%): 2; SubFamily: Single Channel LDO; Iout(Max)(A): 0.15; Vdo(Typ)(mV): 400; Iq(Typ)(mA): 0.003
U101 = CMP-0079610-1: High Performance Synchronous Rectifier Driver for LLC Resonant Converter, D0008A (SOIC-8); Alternate Manufacturer: Texas Instruments; SizeAreaWB_mm2: 56.58; SizeZ_mm: 1.75; SizeX_mm: 4.9; SizeY_mm: 6.2; SizeArea_mm2: 30.38; CompType: IC; AEC Qualified: N; AEC Category: Q200
U102 = UCC25630DDB: Enhanced LLC Resonant Controller with Driver, DDB0014A; Manufacturer: Texas Instruments; SymbolCreator: Altium; CompType: IC; U/M: EA
U103 = VO618A: OPTOISOLATOR 5.3KV TRANS 4-DIP; Manufacturer: Vishay-Semiconductor; CTR (Min): 100%; CTR (Max): 200%; Voltage_Isolation_Vrms: 5300V; CompType: Optocoupler; SizeAreaWB_mm2: 71.064; SizeArea_mm2: 40.304; SizeX_mm: 8.8; SizeY_mm: 4.58; SizeZ_mm: 5
U104 = TLVH431AQDBZR: Low-Voltage Adjustable Precision Shunt Regulator, 80 mA, -40 to 125 degC, 3-pin SOT-23 (DBZ), Green (RoHS & no Sb/Br); Manufacturer: Texas Instruments; Alternate PartNumber: Equivalent; Initial Accuracy @ 25/deg C(%): 1; Iout/Iz(Max)(mA): 80; Rating: Catalog; SubFamily: Shunt Voltage Reference; Temp Coeff(Max)(ppm/ degree C): 129; VO Adj(Max)(V): 18; VO Adj(Min)(V): 1.24

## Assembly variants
001: not fitted C140 C143 D105 D107 D108 D109 Q110 R121 R130 R132 R134 R140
